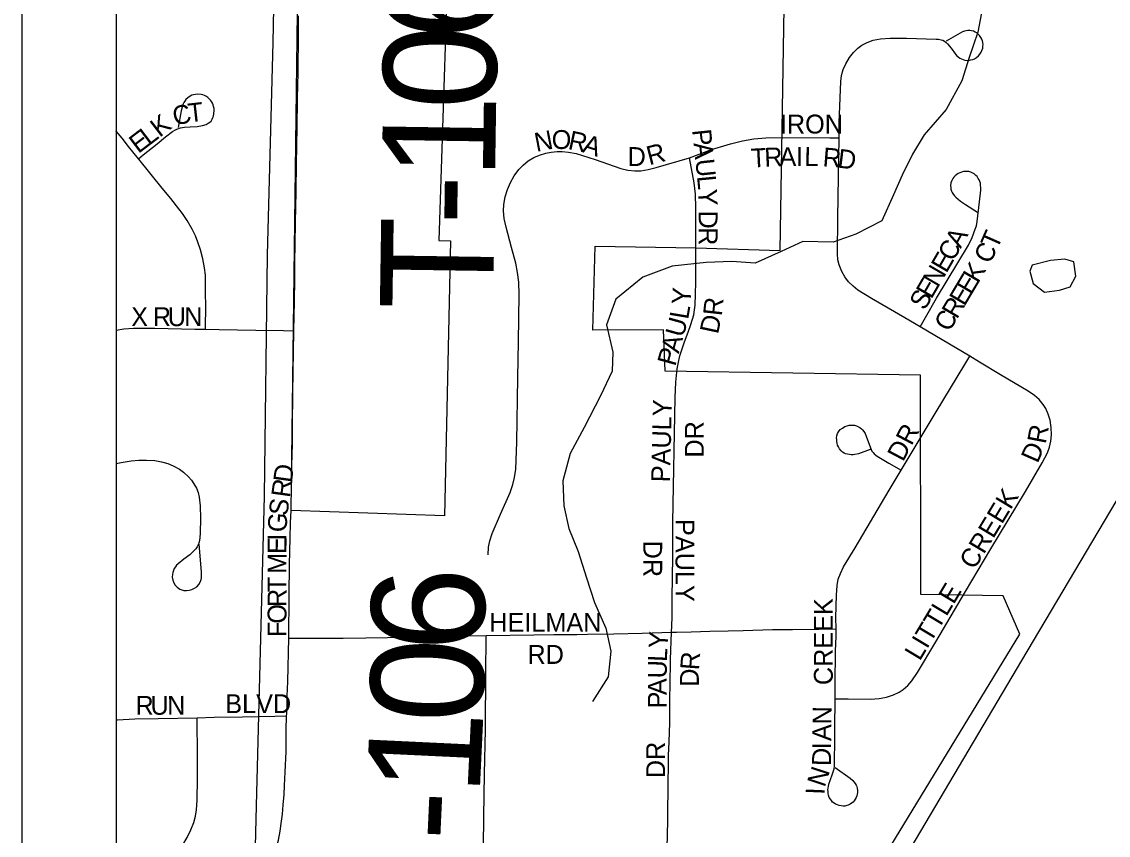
# Model space of a CAD drawing. Extents: x -5.6 to 34, y 0 to 22.
# Drawn here: x 2 to 3.152, y 19.256 to 20.118 of the extents above; entities that cross this region are included whole.
import ezdxf

# ---------------------------------------------------------------- set-up
doc = ezdxf.new("R2010")
doc.units = 0
for name, color, linetype in [('GM_X_City_Street', 7, 'Continuous'), ('GM_X_City_Street_Text', 7, 'Continuous'), ('GM_X_Corporation', 7, 'Continuous'), ('GM_X_Minor_Lake', 7, 'Continuous'), ('GM_X_Minor_River', 7, 'Continuous'), ('GM_X_Rail_Line', 7, 'Continuous'), ('GM_X_Township', 7, 'Continuous'), ('GM_X_Township_Road', 7, 'Continuous'), ('GM_X_Township_Road_Text', 7, 'Continuous'), ('GM_X_Township_Subdivision', 7, 'Continuous'), ('GM_X_Township_Subdivision_Text', 7, 'Continuous'), ('SH_Data', 7, 'Continuous')]:
    doc.layers.add(name, color=color, linetype=linetype)

msp = doc.modelspace()

# ---------------------------------------------------------------- linework, layer by layer
at = {"layer": 'GM_X_City_Street'}
for points in [[(2.8663, 19.9951), (2.8665, 20.0115), (2.868, 20.0548), (2.8689, 20.0613), (2.8706, 20.0677), (2.8733, 20.0737), (2.8774, 20.0804), (2.8814, 20.0856), (2.886, 20.0902), (2.8903, 20.0933), (2.8961, 20.0963), (2.9023, 20.0985), (2.91, 20.0999), (2.9205, 20.1007), (2.9376, 20.1007), (2.9691, 20.0998), (2.9716, 20.0996), (2.9743, 20.0991), (2.9762, 20.0985), (2.9779, 20.0976), (2.9798, 20.0962), (2.9812, 20.0948), (2.985, 20.09), (2.9897, 20.0837), (2.9912, 20.0821), (2.9926, 20.0809), (2.9943, 20.0797), (2.9959, 20.0788), (2.9977, 20.078), (2.9996, 20.0775), (3.0019, 20.0771), (3.0035, 20.0772), (3.006, 20.0776), (3.0079, 20.0782), (3.0099, 20.079), (3.012, 20.0804), (3.0139, 20.0819), (3.0155, 20.0838), (3.0168, 20.0859), (3.0177, 20.0876), (3.0185, 20.0901), (3.0187, 20.092), (3.0188, 20.094), (3.0185, 20.0962), (3.0181, 20.0979), (3.0174, 20.0998), (3.0165, 20.1015), (3.0152, 20.1034), (3.0141, 20.1046), (3.0121, 20.1063), (3.0105, 20.1072), (3.0086, 20.108), (3.0066, 20.1086), (3.0047, 20.1087), (3.0028, 20.1088), (3.0008, 20.1085), (2.999, 20.1081), (2.997, 20.1074), (2.9945, 20.1061), (2.9797, 20.0977)], [(2.1237, 19.9729), (2.1288, 19.977), (2.1434, 19.9887), (2.1525, 19.9963), (2.1599, 20.0017), (2.1621, 20.0031), (2.1644, 20.0043), (2.1681, 20.0057), (2.1724, 20.0065), (2.1785, 20.0069), (2.1861, 20.0073), (2.1915, 20.0082), (2.1953, 20.0093), (2.1976, 20.0105), (2.1995, 20.0118), (2.2007, 20.0129), (2.2019, 20.0148), (2.2026, 20.0166), (2.2031, 20.0182), (2.2036, 20.0204), (2.2039, 20.0243), (2.2038, 20.0263), (2.2034, 20.0282), (2.2029, 20.0301), (2.2021, 20.0319), (2.2011, 20.0337), (2.2002, 20.035), (2.1988, 20.0365), (2.1971, 20.0379), (2.1952, 20.0391), (2.1938, 20.0399), (2.1918, 20.0406), (2.19, 20.041), (2.1861, 20.0414), (2.1843, 20.0411), (2.1822, 20.0407), (2.1803, 20.0402), (2.1786, 20.0393), (2.1759, 20.0376), (2.1739, 20.0357), (2.1728, 20.0341), (2.1719, 20.0326), (2.1708, 20.0303), (2.1701, 20.0277), (2.1691, 20.0236), (2.1658, 20.0062)], [(2.1237, 19.9729), (2.1133, 19.9859), (2.1063, 19.9948), (2.1002, 20.0022), (2.1, 20.0024)], [(2.7076, 19.9739), (2.7311, 19.9826), (2.7512, 19.9888), (2.764, 19.9921), (2.7758, 19.9941), (2.7887, 19.9951), (2.8058, 19.9954), (2.8565, 19.9951), (2.8663, 19.9951)], [(2.9521, 19.795), (2.9359, 19.8045), (2.9007, 19.8248), (2.8862, 19.8338), (2.881, 19.8378), (2.8764, 19.8425), (2.8725, 19.8477), (2.8692, 19.8534), (2.8662, 19.8607), (2.8649, 19.8658), (2.8644, 19.8723), (2.8648, 19.9104), (2.8656, 19.9537), (2.8663, 19.9951)], [(2.4943, 19.5531), (2.4946, 19.5615), (2.4961, 19.5682), (2.4986, 19.5758), (2.5075, 19.5964), (2.5176, 19.6192), (2.5206, 19.6277), (2.5224, 19.6351), (2.5235, 19.644), (2.5247, 19.6727), (2.5259, 19.7411), (2.5264, 19.7791), (2.5271, 19.829), (2.5267, 19.842), (2.5254, 19.8523), (2.5236, 19.8624), (2.5192, 19.8788), (2.5133, 19.9005), (2.5114, 19.9097), (2.5107, 19.9178), (2.5111, 19.9246), (2.5125, 19.9326), (2.5147, 19.9403), (2.5179, 19.9478), (2.522, 19.9549), (2.5268, 19.9614), (2.5315, 19.9663), (2.5368, 19.9706), (2.5427, 19.9742), (2.5489, 19.9769), (2.5554, 19.9789), (2.5611, 19.9798), (2.5676, 19.9806), (2.5728, 19.9806), (2.5796, 19.9801), (2.5876, 19.9785), (2.6078, 19.9722), (2.6349, 19.9625), (2.6424, 19.9607), (2.6499, 19.96), (2.6562, 19.9602), (2.6638, 19.9614), (2.6724, 19.9638), (2.7076, 19.9739)], [(2.1946, 19.7924), (2.195, 19.8183), (2.1949, 19.8296), (2.1949, 19.8393), (2.1946, 19.8496), (2.1936, 19.8574), (2.192, 19.8668), (2.1894, 19.8765), (2.1868, 19.8845), (2.1843, 19.8913), (2.1806, 19.8984), (2.1754, 19.9075), (2.1703, 19.915), (2.1666, 19.9198), (2.1581, 19.9309), (2.1488, 19.9419), (2.1242, 19.9724), (2.1237, 19.9729)], [(2.7143, 19.8786), (2.7144, 19.8864), (2.7144, 19.9208), (2.7139, 19.9355), (2.7125, 19.9474), (2.7076, 19.9739)], [(2.9521, 19.795), (2.9578, 19.8048), (2.9695, 19.8253), (3.0033, 19.8814), (3.0074, 19.8896), (3.0106, 19.8982), (3.0118, 19.902), (3.0126, 19.9064), (3.0152, 19.9274), (3.0164, 19.9396), (3.0165, 19.942), (3.0163, 19.9449), (3.016, 19.947), (3.0155, 19.9487), (3.0147, 19.9507), (3.0138, 19.9522), (3.0125, 19.9541), (3.0113, 19.9553), (3.0093, 19.9569), (3.0073, 19.9581), (3.0058, 19.9586), (3.0038, 19.9593), (3.0019, 19.9594), (2.9999, 19.9595), (2.998, 19.9593), (2.9942, 19.9582), (2.9925, 19.9573), (2.9909, 19.9562), (2.9893, 19.955), (2.988, 19.9535), (2.9869, 19.9521), (2.9856, 19.9499), (2.9847, 19.9473), (2.9844, 19.9444), (2.9846, 19.9425), (2.9848, 19.9408), (2.9854, 19.9387), (2.9861, 19.9371), (2.987, 19.9355), (2.9885, 19.9338), (2.9899, 19.9323), (2.9923, 19.9302), (2.9949, 19.9281), (3.0001, 19.9245), (3.0129, 19.9162)], [(3.0047, 19.7636), (2.9756, 19.7812), (2.9521, 19.795)], [(2.1, 19.7913), (2.1082, 19.7928), (2.1186, 19.7935), (2.141, 19.7933), (2.1833, 19.7924), (2.1946, 19.7924)], [(2.1946, 19.7924), (2.2092, 19.7921), (2.248, 19.7914), (2.2774, 19.7908), (2.2885, 19.7906)], [(2.862, 19.4008), (2.8759, 19.4006), (2.8995, 19.4004), (2.9086, 19.4011), (2.9164, 19.4026), (2.9239, 19.4049), (2.9299, 19.4077), (2.9343, 19.4105), (2.9392, 19.4148), (2.9435, 19.4198), (2.9493, 19.4285), (2.9689, 19.4612), (3.0002, 19.5144), (3.0269, 19.5596), (3.0637, 19.6202), (3.0815, 19.6509), (3.0871, 19.6613), (3.0894, 19.6674), (3.0908, 19.6738), (3.0914, 19.6804), (3.0911, 19.6882), (3.0898, 19.696), (3.088, 19.7023), (3.0853, 19.7083), (3.0825, 19.7127), (3.0782, 19.7177), (3.0733, 19.7221), (3.0668, 19.7265), (3.0374, 19.7439), (3.0149, 19.7574), (3.0047, 19.7636)], [(2.932, 19.6428), (2.9693, 19.7048), (2.9995, 19.7549), (3.0047, 19.7636)], [(2.6899, 19.5877), (2.6925, 19.7198), (2.6933, 19.7363), (2.6947, 19.7504)], [(2.8993, 19.6649), (2.8868, 19.6604), (2.883, 19.6596), (2.8812, 19.6593), (2.8791, 19.6593), (2.8772, 19.6594), (2.8752, 19.6598), (2.8731, 19.6603), (2.8715, 19.6611), (2.8699, 19.6622), (2.8684, 19.6634), (2.8668, 19.6654), (2.8655, 19.6677), (2.8647, 19.6696), (2.8642, 19.6714), (2.8639, 19.6732), (2.8637, 19.6753), (2.8636, 19.6772), (2.8639, 19.6795), (2.8647, 19.6819), (2.8655, 19.6837), (2.8675, 19.6859), (2.8697, 19.6876), (2.8722, 19.6892), (2.8749, 19.6901), (2.8769, 19.6906), (2.8809, 19.6908), (2.8825, 19.6905), (2.8847, 19.69), (2.8881, 19.6883), (2.89, 19.6869), (2.8911, 19.6857), (2.8925, 19.6839), (2.8938, 19.6819), (2.8951, 19.679), (2.8994, 19.6666), (2.9002, 19.6647), (2.9011, 19.6632), (2.9023, 19.6617), (2.9036, 19.6602), (2.9051, 19.6588), (2.9067, 19.6578), (2.9191, 19.6504), (2.932, 19.6428)], [(2.1, 19.65), (2.1054, 19.6512), (2.1161, 19.6528), (2.124, 19.6536), (2.1322, 19.6536), (2.141, 19.6531), (2.1483, 19.6518), (2.1549, 19.65), (2.1606, 19.6474), (2.1671, 19.6439), (2.1716, 19.6408), (2.1767, 19.6358), (2.1799, 19.6322), (2.1823, 19.6285), (2.1851, 19.6238), (2.1869, 19.6194), (2.1882, 19.6145), (2.1891, 19.6051), (2.1894, 19.5919), (2.1891, 19.5765), (2.1886, 19.5712), (2.1879, 19.5667), (2.1869, 19.5638), (2.1858, 19.5617), (2.1844, 19.5597), (2.1822, 19.557), (2.1781, 19.5534), (2.1718, 19.5486), (2.1657, 19.5438), (2.1641, 19.5423), (2.1628, 19.5406), (2.1617, 19.5388), (2.1608, 19.5367), (2.1601, 19.5347), (2.1597, 19.5324), (2.1596, 19.5295), (2.1601, 19.5265), (2.1611, 19.5237), (2.1627, 19.5211), (2.1648, 19.5189), (2.1674, 19.517), (2.1697, 19.5161), (2.1718, 19.5156), (2.1745, 19.5155), (2.1775, 19.5158), (2.1804, 19.5165), (2.1831, 19.5178), (2.1855, 19.5195), (2.1876, 19.5218), (2.1891, 19.5243), (2.1901, 19.5271), (2.1905, 19.529), (2.1906, 19.5315), (2.1906, 19.5351), (2.1879, 19.5644)], [(2.863, 19.475), (2.8629, 19.4867), (2.8634, 19.5104), (2.8641, 19.5208), (2.8654, 19.5273), (2.8676, 19.5335), (2.8711, 19.5405), (2.8833, 19.5608), (2.9195, 19.6219), (2.932, 19.6428)], [(2.283, 19.465), (2.2834, 19.5103), (2.2839, 19.5429), (2.2845, 19.5708), (2.2849, 19.5871), (2.2856, 19.6003)], [(2.7957, 19.474), (2.8169, 19.474), (2.8448, 19.4746), (2.863, 19.475)], [(2.862, 19.4008), (2.862, 19.4161), (2.8626, 19.4512), (2.863, 19.467), (2.863, 19.475)], [(2.687, 19.3902), (2.687, 19.4019), (2.6872, 19.4149), (2.6877, 19.4424), (2.6887, 19.4712)], [(2.862, 19.3278), (2.878, 19.3165), (2.8807, 19.3142), (2.882, 19.3127), (2.8832, 19.3111), (2.8842, 19.3093), (2.8849, 19.3076), (2.8854, 19.3056), (2.8857, 19.3038), (2.8857, 19.3015), (2.8855, 19.2998), (2.8851, 19.2979), (2.8844, 19.2961), (2.8834, 19.2942), (2.8823, 19.2927), (2.881, 19.2912), (2.8795, 19.29), (2.878, 19.289), (2.876, 19.2881), (2.8744, 19.2875), (2.8722, 19.2871), (2.8705, 19.287), (2.8683, 19.2872), (2.8664, 19.2876), (2.8645, 19.2883), (2.8625, 19.2892), (2.861, 19.2901), (2.8594, 19.2913), (2.8581, 19.2928), (2.857, 19.2943), (2.8559, 19.296), (2.8551, 19.2985), (2.8548, 19.3), (2.8546, 19.3024), (2.8545, 19.3043), (2.8547, 19.3064), (2.8549, 19.3079), (2.8554, 19.3102), (2.859, 19.3201), (2.8609, 19.3264), (2.8614, 19.3294), (2.8615, 19.3316), (2.8618, 19.3589), (2.8618, 19.376), (2.862, 19.3938), (2.862, 19.4008)], [(2.1, 19.1754), (2.1012, 19.1758), (2.1072, 19.1791), (2.1125, 19.1834), (2.1193, 19.1896), (2.1406, 19.2111), (2.1652, 19.2385), (2.1707, 19.2458), (2.1754, 19.2537), (2.1793, 19.262), (2.1823, 19.2695), (2.1841, 19.2762), (2.1852, 19.2831), (2.1859, 19.2933), (2.1864, 19.3161), (2.1864, 19.3467), (2.1861, 19.3729), (2.186, 19.3807)], [(2.1, 19.3783), (2.1014, 19.3785), (2.1198, 19.3793), (2.1447, 19.3798), (2.186, 19.3807)], [(2.186, 19.3807), (2.2038, 19.3811), (2.234, 19.3816), (2.2682, 19.3823), (2.2807, 19.3825)]]:
    msp.add_lwpolyline(points, dxfattribs=at)
at = {"layer": 'GM_X_Corporation'}
for points in [[(3.2277, 20.9), (2.1, 20.9), (2.1, 18.226), (2.1688, 18.2231), (2.1708, 18.2767), (2.3867, 18.2751), (2.1, 17.7957), (2.1, 16.1715), (2.1566, 16.1698), (2.1557, 16.0644), (2.1, 16.0648), (2.1, 15.8951), (2.1803, 15.8911), (2.1794, 15.8126), (2.1472, 15.8117), (2.1446, 15.7502), (2.1, 15.7518), (2.1, 15.0823), (2.1322, 15.0813), (2.127, 14.9352), (2.1, 14.9372), (2.1, 14.8511)], [(3.1536, 18.9777), (2.7717, 18.9999), (3.0577, 19.4693), (3.04, 19.5098), (2.9528, 19.5113), (2.9527, 19.7435), (2.6819, 19.7478), (2.6801, 19.7916), (2.6052, 19.7912), (2.6079, 19.8804), (2.7143, 19.8786), (2.8037, 19.8757), (2.8151, 20.562), (3.2274, 20.5511)]]:
    msp.add_lwpolyline(points, dxfattribs=at)
msp.add_lwpolyline([(2.294, 20.2674), (2.4545, 20.2654), (2.442, 19.8863), (2.4544, 19.8859), (2.4479, 19.5945), (2.2856, 19.6003)], close=True, dxfattribs=at)
at = {"layer": 'GM_X_Minor_Lake'}
msp.add_line((3.0838, 19.8317), (3.0999, 19.8337), dxfattribs=at)
msp.add_lwpolyline([(3.0999, 19.8337), (3.1111, 19.8374), (3.117, 19.8485), (3.115, 19.8638), (3.1054, 19.8665), (3.0902, 19.8652), (3.071, 19.8601), (3.0684, 19.8537), (3.0721, 19.8408), (3.0838, 19.8317)], dxfattribs=at)
at = {"layer": 'GM_X_Minor_River'}
for points in [[(2.2695, 20.2798), (2.266, 20.0963), (2.2602, 19.871), (2.257, 19.6153), (2.2485, 19.2874), (2.2423, 19.0438), (2.2144, 19.0427), (2.1857, 19.0432), (2.1665, 19.0444), (2.1529, 19.043), (2.1385, 19.0409), (2.1192, 19.0316), (2.1086, 19.0206), (2.1004, 19.0079), (2.1, 19.0071)], [(3.0196, 20.1407), (3.0134, 20.1072), (3.0041, 20.0801), (2.9964, 20.0554), (2.9799, 20.0252), (2.9563, 19.9984), (2.9439, 19.9778), (2.9331, 19.9555), (2.9239, 19.9348), (2.9115, 19.907), (2.8841, 19.8931), (2.8599, 19.8847), (2.828, 19.8853), (2.8047, 19.8745), (2.7773, 19.8622), (2.7526, 19.8642), (2.7254, 19.8631), (2.6895, 19.859), (2.6581, 19.8476), (2.6297, 19.824), (2.6196, 19.797), (2.6263, 19.768), (2.6259, 19.7479), (2.6134, 19.7217), (2.5961, 19.6883), (2.5812, 19.6605), (2.5734, 19.6318), (2.5745, 19.6053), (2.5797, 19.5812), (2.5896, 19.5569), (2.5987, 19.5287), (2.6069, 19.5029), (2.6192, 19.4754), (2.6243, 19.4512), (2.6214, 19.424), (2.605, 19.3979)]]:
    msp.add_lwpolyline(points, dxfattribs=at)
at = {"layer": 'GM_X_Rail_Line'}
msp.add_lwpolyline([(2.1, 17.8198), (3.0599, 19.4414), (3.6284, 20.3994)], dxfattribs=at)
at = {"layer": 'GM_X_Township'}
msp.add_lwpolyline([(3.0636, 14.1), (8.9, 14.1), (8.9, 20.9), (2.1, 20.9), (2.1, 16.9108), (2.7242, 16.8707), (3.1388, 16.8616), (3.0745, 14.7121)], close=True, dxfattribs=at)
at = {"layer": 'GM_X_Township_Road'}
for points in [[(2.2885, 19.7906), (2.2891, 19.822), (2.2893, 19.8449), (2.2895, 19.8512), (2.2895, 19.8566), (2.2895, 19.8664), (2.2897, 19.8793), (2.2901, 19.9089), (2.2904, 19.9181), (2.2907, 19.9417), (2.2916, 19.9889), (2.2918, 20.0047), (2.292, 20.0148), (2.2921, 20.0268), (2.2923, 20.0385), (2.2926, 20.0491), (2.2929, 20.0657), (2.2933, 20.1042), (2.2935, 20.1245)], [(2.2856, 19.6003), (2.2856, 19.6048), (2.2857, 19.6103), (2.2859, 19.6177), (2.286, 19.6237), (2.2862, 19.6354), (2.2863, 19.6481), (2.2869, 19.6706), (2.2871, 19.6894), (2.2874, 19.7253), (2.2885, 19.7902), (2.2885, 19.7906)], [(2.6887, 19.4712), (2.6939, 19.4713), (2.7096, 19.4717), (2.7292, 19.4722), (2.7488, 19.4726), (2.7645, 19.4731), (2.7957, 19.474)], [(2.2807, 19.3825), (2.2808, 19.3848), (2.2812, 19.3964), (2.2814, 19.4035), (2.2819, 19.4189), (2.283, 19.465)], [(2.283, 19.465), (2.3162, 19.4651), (2.3406, 19.4649), (2.3648, 19.4654), (2.3875, 19.4657)], [(2.5882, 19.4688), (2.5996, 19.4691), (2.6275, 19.4696), (2.6575, 19.4704), (2.6784, 19.4709), (2.6887, 19.4712)], [(2.2543, 19.2036), (2.2587, 19.2118), (2.2618, 19.219), (2.2647, 19.2261), (2.266, 19.2297), (2.2674, 19.2333), (2.2698, 19.2412), (2.2722, 19.2509), (2.2738, 19.2606), (2.275, 19.2685), (2.2756, 19.2735), (2.2762, 19.2786), (2.277, 19.2885), (2.278, 19.2994), (2.2786, 19.309), (2.2792, 19.3228), (2.2802, 19.3448), (2.2802, 19.3478), (2.2803, 19.3673), (2.2807, 19.3825)]]:
    msp.add_lwpolyline(points, dxfattribs=at)
at = {"layer": 'GM_X_Township_Subdivision'}
for points in [[(2.7066, 19.7903), (2.7088, 19.7962), (2.7109, 19.8028), (2.7123, 19.8076), (2.7131, 19.8128), (2.7136, 19.8177), (2.7142, 19.8293), (2.7145, 19.8421), (2.7143, 19.8786)], [(2.6947, 19.7504), (2.696, 19.7575), (2.6976, 19.764), (2.702, 19.7778), (2.7066, 19.7903)], [(2.6899, 19.5493), (2.6899, 19.5877)], [(2.6887, 19.4712), (2.689, 19.4779), (2.6893, 19.4875), (2.6893, 19.4956), (2.6894, 19.5054), (2.6896, 19.5312), (2.6899, 19.5493)], [(2.3875, 19.4657), (2.428, 19.4665), (2.445, 19.4668), (2.466, 19.4673), (2.4922, 19.4678)], [(2.4846, 19.017), (2.4848, 19.0299), (2.4856, 19.0722), (2.4867, 19.1343), (2.4875, 19.165), (2.4885, 19.2076), (2.4893, 19.2437), (2.4898, 19.2759), (2.4906, 19.3207), (2.4914, 19.3681), (2.4919, 19.4301), (2.4922, 19.4639), (2.4922, 19.4678)], [(2.4922, 19.4678), (2.5429, 19.4685), (2.5641, 19.4688), (2.5882, 19.4688)], [(2.6841, 19.2416), (2.6843, 19.2576), (2.6846, 19.2706), (2.6849, 19.2861), (2.6851, 19.3007), (2.6851, 19.314), (2.6854, 19.3275), (2.6856, 19.3406), (2.6862, 19.3552), (2.6867, 19.3753), (2.687, 19.3902)]]:
    msp.add_lwpolyline(points, dxfattribs=at)
at = {"layer": 'SH_Data'}
for p, q in [((2, 21), (2, 14)), ((2.1, 20.9), (2.1, 14.1))]:
    msp.add_line(p, q, dxfattribs=at)

# ---------------------------------------------------------------- texts
at = {"layer": 'GM_X_City_Street_Text'}
for s, rotation, p in [('C', 13.1821, (2.1624, 20.0078)), ('T', 6.4609, (2.1772, 20.0114)), ('K', 37.7303, (2.1461, 19.995)), ('IRON', 0, (2.8035, 19.9997)), ('E', 37.3453, (2.1236, 19.9779)), ('L', 37.3647, (2.1348, 19.9864)), ('N', 10.8641, (2.5454, 19.9802)), ('O', 359.5191, (2.5616, 19.9834)), ('R', 347.8374, (2.5781, 19.9834)), ('P', 275.9661, (2.7105, 20.0034)), ('A', 342.5326, (2.5931, 19.9802)), ('D', 359.8251, (2.6421, 19.9653)), ('R', 14.4204, (2.6651, 19.966)), ('A', 275.9564, (2.7119, 19.9894)), ('T', 2.9798, (2.7734, 19.9636)), ('R', 2.3566, (2.7874, 19.9644)), ('A', 1.0055, (2.8031, 19.965)), ('I', 0.1748, (2.8207, 19.9653)), ('L', 359.5082, (2.8294, 19.9653)), ('R', 355.3573, (2.8484, 19.965)), ('D', 353.0539, (2.864, 19.9637)), ('U', 275.9702, (2.7138, 19.9719)), ('L', 275.5556, (2.7156, 19.9544)), ('Y', 271.9019, (2.7169, 19.9408)), ('D', 270, (2.7175, 19.9181)), ('R', 269.994, (2.7175, 19.9005)), ('A', 61.1439, (2.9951, 19.8772)), ('T', 66.2063, (3.0338, 19.876)), ('C', 59.9026, (2.9869, 19.8631)), ('C', 61.4003, (3.0255, 19.8604)), ('E', 59.8891, (2.9799, 19.8509)), ('K', 59.462, (3.0135, 19.8401)), ('N', 59.9102, (2.9711, 19.8357)), ('E', 59.8891, (2.964, 19.8235)), ('E', 59.3876, (3.0063, 19.8279)), ('S', 59.8891, (2.9569, 19.8114)), ('E', 59.4014, (2.9991, 19.8158)), ('R', 59.3925, (2.9911, 19.8022)), ('X', 0.0437, (2.116, 19.7956)), ('R', 0, (2.1389, 19.7956)), ('U', 0, (2.1547, 19.7956)), ('N', 0, (2.1723, 19.7956)), ('C', 59.3694, (2.983, 19.7885)), ('PAULY', 88.7505, (2.6871, 19.63)), ('DR', 90, (2.7229, 19.6563)), ('DR', 62.1086, (2.934, 19.651)), ('R', 79.1424, (3.0851, 19.6701)), ('D', 66.2217, (3.0766, 19.6494)), ('D', 82.1113, (2.2862, 19.6289)), ('R', 82.0968, (2.2841, 19.6132)), ('CREEK', 58.8637, (3.0096, 19.5366)), ('S', 82.492, (2.2815, 19.594)), ('G', 87.0263, (2.2806, 19.5768)), ('I', 89.9573, (2.2806, 19.5683)), ('E', 89.9453, (2.2806, 19.5542)), ('M', 89.9636, (2.2806, 19.5331)), ('T', 89.9707, (2.2806, 19.5137)), ('LITTLE', 59.0346, (2.9517, 19.44)), ('R', 89.9514, (2.2806, 19.4979)), ('O', 89.9563, (2.2806, 19.4803)), ('CREEK', 90, (2.8596, 19.4152)), ('F', 89.9727, (2.2805, 19.4662)), ('Y', 86.6759, (2.6843, 19.4536)), ('L', 87.6493, (2.6837, 19.4396)), ('U', 89.6284, (2.6836, 19.4222)), ('R', 85.6479, (2.7177, 19.4306)), ('D', 89.6939, (2.7176, 19.4134)), ('A', 89.9587, (2.6836, 19.4046)), ('R', 0.1214, (2.1206, 19.3837)), ('U', 0.1279, (2.1365, 19.3838)), ('N', 0.1312, (2.1541, 19.3838)), ('BLVD', 0, (2.2157, 19.3855)), ('P', 89.9453, (2.6836, 19.3905)), ('N', 89.5191, (2.8581, 19.3735)), ('A', 89.5191, (2.8579, 19.3559)), ('D', 88.9004, (2.8575, 19.3293)), ('I', 89.5626, (2.8578, 19.3471)), ('N', 71.7724, (2.8509, 19.3062)), ('I', 87.5959, (2.8508, 19.2988))]:
    msp.add_text(s, height=0.02, rotation=rotation, dxfattribs=at).set_placement(p)
at = {"layer": 'GM_X_Township_Road_Text'}
for s, rotation, p in [('6', 89.5688, (2.5036, 20.0985)), ('0', 89.3538, (2.5027, 20.0246)), ('1', 89.1297, (2.5016, 19.9508)), ('-', 89.1366, (2.5009, 19.902)), ('T', 89.1343, (2.4995, 19.8124)), ('6', 89.7677, (2.4905, 19.4507)), ('0', 88.6606, (2.4888, 19.3743)), ('1', 87.293, (2.4852, 19.2973)), ('-', 87.3623, (2.4829, 19.2481))]:
    msp.add_text(s, height=0.12, rotation=rotation, dxfattribs=at).set_placement(p)
at = {"layer": 'GM_X_Township_Subdivision_Text'}
for s, rotation, p in [('Y', 86.6149, (2.7088, 19.8182)), ('R', 83.8021, (2.7419, 19.8058)), ('L', 80.4704, (2.7062, 19.802)), ('D', 77.8884, (2.7379, 19.7864)), ('U', 74.4462, (2.701, 19.7828)), ('P', 74.4262, (2.6925, 19.7523)), ('A', 74.4209, (2.6963, 19.7659)), ('PAULY', 270, (2.6929, 19.5912)), ('DR', 270, (2.6588, 19.5683)), ('HEILMAN', 0, (2.4955, 19.4717)), ('RD', 0, (2.536, 19.4377)), ('DR', 90, (2.6818, 19.3166))]:
    msp.add_text(s, height=0.02, rotation=rotation, dxfattribs=at).set_placement(p)

doc.saveas('drawing.dxf')
